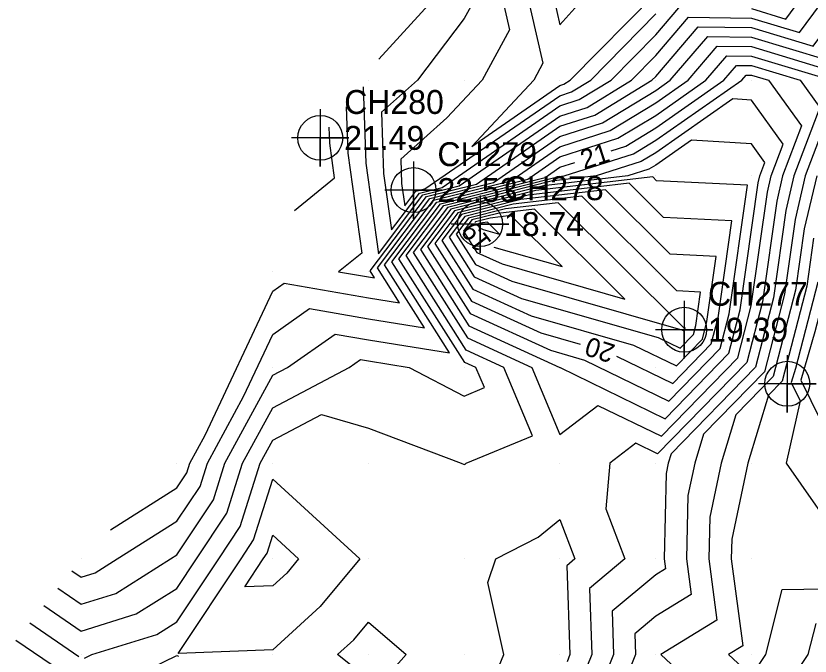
# Model space of a CAD drawing. Extents: x 2531902 to 2533249, y 715219 to 716099.
# Drawn here: x 2532833.2 to 2532916.1, y 715819.8 to 715886.7 of the extents above; entities that cross this region are included whole.
import ezdxf

# ---------------------------------------------------------------- set-up
doc = ezdxf.new("R2010")
doc.units = 0
for name, color, linetype in [('DTM Contours Major', 7, 'Continuous'), ('DTM Contours Major Text', 7, 'Continuous'), ('DTM Contours Minor', 7, 'Continuous'), ('Exist DTM QL2 LIDAR Elevation Point', 7, 'Continuous'), ('Exist DTM Regular Point CELL', 7, 'Continuous'), ('Exist DTM Regular Point Cogo Elevation', 7, 'Continuous'), ('Exist DTM Regular Point Cogo Number', 7, 'Continuous')]:
    doc.layers.add(name, color=color, linetype=linetype)

msp = doc.modelspace()

# ---------------------------------------------------------------- linework, layer by layer
at = {"layer": 'DTM Contours Major'}
for points in [[(2532871.1, 715882.2), (2532880, 715891.997), (2532883.708, 715896.292), (2532890, 715895.906), (2532894.7, 715895.3), (2532900, 715896.962), (2532902.958, 715897.042), (2532903.124, 715900), (2532904.456, 715903.247)], [(2532869.44, 715879.33), (2532869.714, 715871.324), (2532871.035, 715861.876), (2532875.683, 715868.03), (2532879.483, 715868.988), (2532890, 715876.258), (2532892.834, 715877.166), (2532897.48, 715880), (2532900, 715882.576), (2532903.422, 715886.578), (2532910, 715886.491), (2532915.024, 715884.976), (2532918.699, 715890), (2532920, 715890.898), (2532928.234, 715891.766), (2532930, 715892.052), (2532936.669, 715890), (2532935.786, 715886.026)], [(2532933.367, 715883.205), (2532930, 715881.047), (2532929.63, 715880), (2532927.126, 715872.874), (2532921.832, 715870), (2532923.637, 715866.363), (2532920, 715868.392), (2532918.408, 715861.592), (2532918.084, 715859.319), (2532916.635, 715853.705), (2532915.167, 715848.687), (2532918.329, 715842.217), (2532917.825, 715840), (2532920, 715836.892), (2532925.534, 715834.466), (2532922.534, 715840), (2532927.6, 715842.4), (2532927.178, 715850), (2532924.657, 715855.343), (2532930, 715857.74), (2532931.581, 715856.223)], [(2532895.348, 715872.639), (2532896.872, 715873.128), (2532900, 715875.036), (2532907.117, 715880), (2532908.446, 715881.554), (2532910, 715881.533), (2532915.086, 715880), (2532917.145, 715877.145), (2532914.441, 715870), (2532913.598, 715866.402), (2532912.297, 715857.26), (2532910.431, 715850.037), (2532901.604, 715840.969), (2532901.31, 715840), (2532901.08, 715838.92), (2532900.884, 715830), (2532901.019, 715828.981), (2532900, 715828.354), (2532895.449, 715824.551), (2532895.611, 715820), (2532894.002, 715815.998), (2532894.246, 715811.122)], [(2532836.095, 715825.138), (2532840, 715822.469), (2532845.749, 715824.251), (2532850, 715826.927), (2532852.044, 715830), (2532855.218, 715834.782), (2532856.852, 715840), (2532860, 715845.799), (2532867.997, 715850), (2532869.173, 715850.827), (2532870, 715850.682), (2532874.259, 715850), (2532880, 715847.018), (2532882.108, 715847.892), (2532881.226, 715850), (2532880.059, 715850.535), (2532873.183, 715861.358), (2532877.515, 715867.093), (2532888.445, 715869.85), (2532890, 715870.925), (2532891.539, 715871.418)], [(2532897.22, 715869.238), (2532886.698, 715868.011), (2532879.346, 715866.156), (2532876.93, 715862.957), (2532880.766, 715856.919), (2532887.994, 715853.6), (2532892.103, 715852.424)], [(2532895.895, 715851.186), (2532901.775, 715848.325), (2532905.802, 715852.462), (2532906.509, 715855.201), (2532907.949, 715865.313), (2532900.801, 715865.672), (2532897.22, 715869.238)], [(2532890.236, 715860.535), (2532884.888, 715865.859), (2532882.704, 715865.605), (2532881.178, 715865.22), (2532881.116, 715865.138)], [(2532883.101, 715862.576), (2532890.236, 715860.535)]]:
    msp.add_lwpolyline(points, dxfattribs=at)
at = {"layer": 'DTM Contours Minor'}
for points in [[(2532890, 715890.484), (2532889.485, 715890.515), (2532889.04, 715890), (2532890, 715885.796), (2532893.754, 715890), (2532890, 715890.484)], [(2532883.658, 715890), (2532884.74, 715885.26), (2532881.87, 715880), (2532878.184, 715876.065), (2532873.375, 715871.775), (2532873.463, 715869.226), (2532873.792, 715866.871), (2532874.951, 715868.405), (2532875.898, 715868.643), (2532890, 715878.391), (2532891.218, 715878.782), (2532893.216, 715880), (2532900, 715886.935)], [(2532886.349, 715890), (2532888.228, 715881.772), (2532887.261, 715880), (2532880.795, 715873.095), (2532890, 715879.458), (2532890.41, 715879.59), (2532891.083, 715880), (2532900, 715889.115)], [(2532910, 715887.483), (2532913.604, 715886.396), (2532916.241, 715890)], [(2532881.253, 715888.747), (2532880, 715886.452), (2532875.11, 715880), (2532871.369, 715876.663), (2532871.588, 715870.275), (2532872.414, 715864.373), (2532875.317, 715868.217), (2532877.69, 715868.816), (2532890, 715877.325), (2532892.026, 715877.974), (2532895.348, 715880), (2532900, 715884.756), (2532902.418, 715887.582)], [(2532867.673, 715877.217), (2532867.839, 715872.374), (2532869.297, 715861.953), (2532866.884, 715860), (2532870, 715859.454), (2532870.65, 715859.35), (2532870.186, 715860.08), (2532876.049, 715867.842), (2532881.275, 715869.161), (2532890, 715875.192), (2532893.641, 715876.359), (2532899.612, 715880), (2532900, 715880.397), (2532904.427, 715885.573), (2532910, 715885.5), (2532916.443, 715883.557), (2532920, 715888.418)], [(2532843.047, 715833.047), (2532850, 715837.433), (2532851.024, 715838.976), (2532851.345, 715840), (2532852.942, 715842.942), (2532860, 715857.961), (2532861.197, 715858.803), (2532870, 715857.261), (2532873.261, 715856.739), (2532870.936, 715860.399), (2532876.416, 715867.655), (2532883.068, 715869.333), (2532890, 715874.125), (2532894.449, 715875.551), (2532900, 715878.936), (2532901.525, 715880), (2532905.432, 715884.568), (2532910, 715884.508), (2532917.863, 715882.137)], [(2532839.01, 715828.768), (2532840, 715828.091), (2532841.457, 715828.543), (2532843.772, 715830), (2532850, 715833.929), (2532852.422, 715837.578), (2532853.181, 715840), (2532856.957, 715846.957), (2532860, 715853.432), (2532863.856, 715856.144), (2532870, 715855.068), (2532875.873, 715854.127), (2532871.685, 715860.719), (2532876.782, 715867.468), (2532884.86, 715869.506), (2532890, 715873.058), (2532895.257, 715874.743), (2532900, 715877.636), (2532903.389, 715880), (2532906.437, 715883.563), (2532910, 715883.517), (2532919.282, 715880.718)], [(2532837.553, 715826.953), (2532840, 715825.28), (2532843.603, 715826.397), (2532849.326, 715830), (2532850, 715830.425), (2532853.82, 715836.18), (2532855.017, 715840), (2532860, 715849.181), (2532861.559, 715850), (2532866.514, 715853.486), (2532870, 715852.875), (2532878.484, 715851.516), (2532872.434, 715861.039), (2532877.148, 715867.28), (2532886.653, 715869.678), (2532890, 715871.992), (2532896.064, 715873.936), (2532900, 715876.336), (2532905.253, 715880), (2532907.441, 715882.559), (2532910, 715882.525), (2532918.374, 715880)], [(2532840.362, 715819.638), (2532841.105, 715820), (2532847.895, 715822.105), (2532850, 715823.43), (2532854.369, 715830), (2532856.616, 715833.384), (2532858.688, 715840), (2532860, 715842.417), (2532865.092, 715845.092), (2532870, 715843.644), (2532879.689, 715840), (2532880, 715839.853), (2532880.097, 715839.903), (2532880.217, 715840), (2532887.134, 715842.866), (2532884.148, 715850), (2532880.201, 715851.812), (2532873.933, 715861.678), (2532877.881, 715866.906), (2532889.894, 715869.936), (2532890.442, 715870), (2532897.68, 715872.32), (2532900, 715873.735), (2532908.981, 715880), (2532909.451, 715880.549), (2532910, 715880.542), (2532911.797, 715880), (2532915.235, 715875.235), (2532913.254, 715870), (2532912.636, 715867.364), (2532911.139, 715856.848), (2532909.505, 715850.522), (2532900.207, 715840.969), (2532897.916, 715842.084), (2532895.196, 715840), (2532894.785, 715835.215), (2532896.767, 715830), (2532893.08, 715826.92), (2532893.326, 715820), (2532892.373, 715817.627)], [(2532919.055, 715879.055), (2532915.628, 715870), (2532914.56, 715865.44), (2532913.454, 715857.672), (2532911.357, 715849.552), (2532904.996, 715843.017), (2532904.079, 715840), (2532903.366, 715836.634), (2532903.22, 715830), (2532903.71, 715826.29), (2532900, 715824.006), (2532897.817, 715822.183), (2532897.895, 715820), (2532895.632, 715814.368)], [(2532889.095, 715869.455), (2532878.247, 715866.718), (2532874.682, 715861.998), (2532880.342, 715853.089), (2532887.07, 715850), (2532890, 715843), (2532893.964, 715846.036), (2532900.599, 715842.808), (2532908.58, 715851.007), (2532909.982, 715856.436), (2532911.675, 715868.325), (2532912.067, 715870), (2532913.325, 715873.325), (2532910, 715877.933), (2532908.051, 715878.051), (2532900, 715872.435), (2532898.487, 715871.513), (2532893.769, 715870), (2532889.095, 715869.455)], [(2532862.277, 715866.409), (2532866.471, 715869.804), (2532865.965, 715873.423), (2532865.907, 715875.105)], [(2532888.296, 715868.974), (2532878.614, 715866.531), (2532875.431, 715862.317), (2532880.483, 715854.365), (2532889.991, 715850), (2532890, 715849.98), (2532890.012, 715849.988), (2532900.991, 715844.647), (2532907.654, 715851.492), (2532908.824, 715856.025), (2532910.713, 715869.287), (2532910.879, 715870), (2532911.415, 715871.415), (2532910, 715873.376), (2532903.752, 715873.752), (2532900, 715871.135), (2532899.295, 715870.705), (2532897.096, 715870), (2532888.296, 715868.974)], [(2532899.686, 715869.914), (2532887.497, 715868.492), (2532878.98, 715866.344), (2532876.18, 715862.637), (2532880.625, 715855.642), (2532888.999, 715851.797), (2532892.56, 715850.778), (2532901.383, 715846.486), (2532906.728, 715851.977), (2532907.666, 715855.613), (2532909.578, 715869.035), (2532900.09, 715869.511), (2532899.686, 715869.914)], [(2532916.815, 715870), (2532915.522, 715864.478), (2532914.612, 715858.083), (2532912.283, 715849.067), (2532908.388, 715845.066), (2532906.849, 715840), (2532905.651, 715834.349), (2532905.555, 715830), (2532906.401, 715823.599), (2532900.554, 715820), (2532910, 715811.181), (2532915.941, 715820), (2532916.756, 715823.244)], [(2532894.753, 715868.562), (2532885.9, 715867.53), (2532879.712, 715865.969), (2532877.679, 715863.277), (2532880.907, 715858.195), (2532886.99, 715855.402), (2532897.696, 715852.339), (2532902.167, 715850.164), (2532904.876, 715852.947), (2532905.351, 715854.789), (2532906.32, 715861.592), (2532901.512, 715861.833), (2532894.753, 715868.562)], [(2532892.287, 715867.887), (2532885.101, 715867.048), (2532880.079, 715865.782), (2532878.428, 715863.596), (2532881.048, 715859.472), (2532885.986, 715857.205), (2532900.264, 715853.12), (2532902.559, 715852.003), (2532903.95, 715853.432), (2532904.194, 715854.378), (2532904.691, 715857.87), (2532902.223, 715857.994), (2532892.287, 715867.887)], [(2532889.821, 715867.211), (2532884.302, 715866.567), (2532880.445, 715865.594), (2532879.177, 715863.916), (2532881.19, 715860.749), (2532884.982, 715859.008), (2532902.831, 715853.9), (2532902.951, 715853.842), (2532903.024, 715853.917), (2532903.036, 715853.966), (2532903.062, 715854.148), (2532902.934, 715854.154), (2532889.821, 715867.211)], [(2532896.784, 715857.146), (2532887.355, 715866.535), (2532883.503, 715866.086), (2532880.811, 715865.407), (2532879.927, 715864.236), (2532881.331, 715862.025), (2532883.977, 715860.81), (2532896.784, 715857.146)], [(2532883.688, 715863.924), (2532882.422, 715865.184), (2532881.905, 715865.123), (2532881.544, 715865.032), (2532881.425, 715864.875), (2532881.614, 715864.578), (2532881.969, 715864.415), (2532883.688, 715863.924)], [(2532916.484, 715863.516), (2532915.769, 715858.495), (2532913.209, 715848.582), (2532911.78, 715847.114), (2532909.619, 715840), (2532907.936, 715832.064), (2532907.89, 715830), (2532909.092, 715820.908), (2532907.618, 715820), (2532910, 715817.776), (2532911.498, 715820), (2532913.207, 715826.793), (2532920, 715826.92)], [(2532916.927, 715858.907), (2532914.601, 715849.901), (2532914.167, 715848.415), (2532915.103, 715846.5), (2532913.623, 715840), (2532920, 715830.89)], [(2532850.132, 715820.132), (2532856.695, 715830), (2532858.014, 715831.986), (2532860, 715838.327), (2532869.085, 715830), (2532864.969, 715825.031), (2532860, 715820.506), (2532850.132, 715820.132)], [(2532882.939, 715817.061), (2532884.154, 715820), (2532882.453, 715827.547), (2532883.304, 715830), (2532887.712, 715832.288), (2532890, 715834.115), (2532891.564, 715830), (2532890.712, 715829.288), (2532891.042, 715820), (2532890.743, 715819.257)], [(2532857.076, 715827.076), (2532859.021, 715830), (2532859.411, 715830.589), (2532860, 715832.467), (2532862.692, 715830), (2532861.472, 715828.528), (2532860, 715827.187), (2532857.076, 715827.076)], [(2532834.638, 715823.324), (2532839.764, 715819.819)], [(2532868.466, 715821.534), (2532870, 715823.386), (2532873.936, 715820), (2532872.081, 715817.919), (2532870, 715817.455), (2532866.782, 715820), (2532868.466, 715821.534)], [(2532833.181, 715821.509), (2532837.825, 715818.333)], [(2532843.333, 715816.667), (2532850, 715819.916), (2532850.169, 715819.831)]]:
    msp.add_lwpolyline(points, dxfattribs=at)
at = {"layer": 'Exist DTM QL2 LIDAR Elevation Point'}
for p, q in [((2532870, 715880), (2532870, 715880)), ((2532880, 715880), (2532880, 715880)), ((2532890, 715880), (2532890, 715880)), ((2532900, 715880), (2532900, 715880)), ((2532910, 715880), (2532910, 715880)), ((2532880, 715870), (2532880, 715870)), ((2532890, 715870), (2532890, 715870)), ((2532900, 715870), (2532900, 715870)), ((2532910, 715870), (2532910, 715870)), ((2532860, 715860), (2532860, 715860)), ((2532870, 715860), (2532870, 715860)), ((2532880, 715860), (2532880, 715860)), ((2532890, 715860), (2532890, 715860)), ((2532900, 715860), (2532900, 715860)), ((2532910, 715860), (2532910, 715860)), ((2532860, 715850), (2532860, 715850)), ((2532870, 715850), (2532870, 715850)), ((2532880, 715850), (2532880, 715850)), ((2532890, 715850), (2532890, 715850)), ((2532900, 715850), (2532900, 715850)), ((2532850, 715840), (2532850, 715840)), ((2532860, 715840), (2532860, 715840)), ((2532870, 715840), (2532870, 715840)), ((2532880, 715840), (2532880, 715840)), ((2532890, 715840), (2532890, 715840)), ((2532900, 715840), (2532900, 715840)), ((2532910, 715840), (2532910, 715840)), ((2532840, 715830), (2532840, 715830)), ((2532850, 715830), (2532850, 715830)), ((2532860, 715830), (2532860, 715830)), ((2532870, 715830), (2532870, 715830)), ((2532880, 715830), (2532880, 715830)), ((2532890, 715830), (2532890, 715830)), ((2532900, 715830), (2532900, 715830)), ((2532910, 715830), (2532910, 715830)), ((2532840, 715820), (2532840, 715820)), ((2532850, 715820), (2532850, 715820)), ((2532860, 715820), (2532860, 715820)), ((2532870, 715820), (2532870, 715820)), ((2532880, 715820), (2532880, 715820)), ((2532890, 715820), (2532890, 715820)), ((2532900, 715820), (2532900, 715820)), ((2532910, 715820), (2532910, 715820))]:
    msp.add_line(p, q, dxfattribs=at)
at = {"layer": 'Exist DTM Regular Point CELL'}
for points in [[(2532864.968, 715876.981), (2532864.968, 715870.981), (2532864.968, 715873.981), (2532867.968, 715873.981), (2532861.968, 715873.981)], [(2532874.707, 715871.529), (2532874.707, 715865.529), (2532874.707, 715868.529), (2532877.707, 715868.529), (2532871.707, 715868.529)], [(2532881.658, 715867.974), (2532881.658, 715861.974), (2532881.658, 715864.974), (2532884.658, 715864.974), (2532878.658, 715864.974)], [(2532902.973, 715856.943), (2532902.973, 715850.943), (2532902.973, 715853.943), (2532905.973, 715853.943), (2532899.973, 715853.943)], [(2532913.746, 715851.301), (2532913.746, 715845.301), (2532913.746, 715848.301), (2532916.746, 715848.301), (2532910.746, 715848.301)]]:
    msp.add_lwpolyline(points, dxfattribs=at)
for centre in [(2532864.968, 715873.981), (2532874.707, 715868.529), (2532881.658, 715864.974), (2532902.973, 715853.943), (2532913.746, 715848.301)]:
    msp.add_circle(centre, 2.344, dxfattribs=at)

# ---------------------------------------------------------------- texts
at = {"layer": 'DTM Contours Major Text'}
for s, rotation, p in [('21', 17.77421, (2532892.519, 715870.682)), ('19', 127.7575, (2532882.943, 715863.069)), ('20', 161.91016, (2532895.885, 715852.319))]:
    msp.add_text(s, height=2, rotation=rotation, dxfattribs=at).set_placement(p)
at = {"layer": 'Exist DTM Regular Point Cogo Elevation'}
for s, p in [('21.49', (2532867.468, 715872.731)), ('22.53', (2532877.207, 715867.279)), ('18.74', (2532884.158, 715863.724)), ('19.39', (2532905.473, 715852.693))]:
    msp.add_text(s, height=2.5, dxfattribs=at).set_placement(p)
at = {"layer": 'Exist DTM Regular Point Cogo Number'}
for s, p in [('CH280', (2532867.468, 715876.481)), ('CH279', (2532877.207, 715871.029)), ('CH278', (2532884.158, 715867.474)), ('CH277', (2532905.473, 715856.443))]:
    msp.add_text(s, height=2.5, dxfattribs=at).set_placement(p)

doc.saveas('drawing.dxf')
